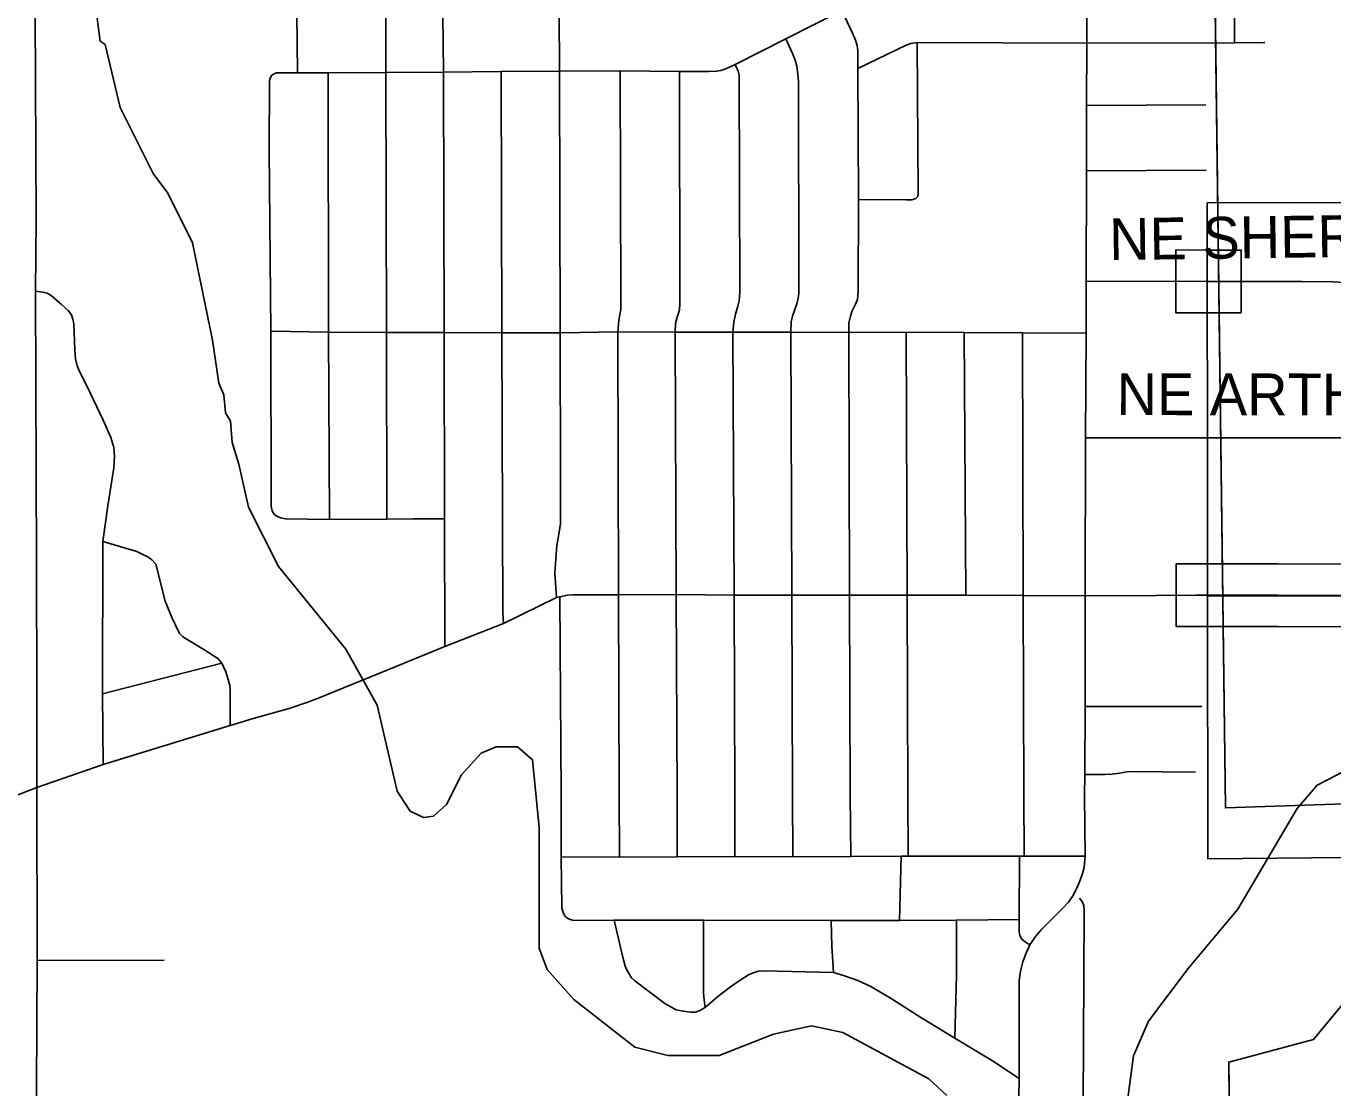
# Model space of a CAD drawing. Extents: x -1403959 to 81668, y -1400582 to 11018.
# Drawn here: x 7531.9 to 7652.7, y 8382.1 to 8480.3 of the extents above; entities that cross this region are included whole.
import ezdxf

# ---------------------------------------------------------------- set-up
doc = ezdxf.new("R2010")
doc.units = 0
for name, color, linetype in [('tdCiCityDivCarto', 7, 'Continuous'), ('tdCiCoBndryTxt', 7, 'Continuous'), ('tdCiRRCL', 7, 'Continuous'), ('tdCiSectLine', 7, 'Continuous'), ('tdCiSectNmbr', 7, 'Continuous'), ('tdCiSectTwpRng', 7, 'Continuous'), ('tdCoCityStreetMajor', 7, 'Continuous'), ('tdCoClipBndry', 7, 'Continuous'), ('tdCoSectNmbr', 7, 'Continuous'), ('tdCoSurfBitum', 7, 'Continuous'), ('tdCoTwpNameTxt', 7, 'Continuous')]:
    doc.layers.add(name, color=color, linetype=linetype)

msp = doc.modelspace()

# ---------------------------------------------------------------- linework, layer by layer
at = {"layer": 'tdCiCityDivCarto'}
for points in [[(7641.31, 8456.71), (7649.82, 8456.69), (7652.72, 8456.68), (7653.72, 8456.62), (7654.52, 8456.5), (7655.07, 8456.37), (7655.61, 8456.12), (7655.96, 8455.95), (7656.41, 8455.67), (7656.79, 8455.33), (7657, 8454.96)], [(7641.23, 8442.26), (7659.37, 8442.25)]]:
    msp.add_lwpolyline(points, dxfattribs=at)
at = {"layer": 'tdCiCoBndryTxt'}
for points in [[(7641.08, 8456.71), (7641.31, 8456.71)], [(7641.11, 8427.7), (7647.61, 8427.71), (7660.14, 8427.68)]]:
    msp.add_lwpolyline(points, dxfattribs=at)
at = {"layer": 'tdCiRRCL'}
msp.add_lwpolyline([(7653.92, 8403.46), (7641.13, 8403.32), (7641.11, 8427.7), (7641.09, 8442.26), (7641.08, 8456.71), (7641.07, 8463.96), (7654.26, 8463.99)], dxfattribs=at)
at = {"layer": 'tdCiSectLine'}
for points in [[(7644.21, 8453.81), (7641.31, 8453.81), (7641.08, 8453.81), (7638.18, 8453.81), (7638.18, 8459.62), (7641.08, 8459.61), (7641.32, 8459.61), (7644.22, 8459.61), (7644.21, 8453.81)], [(7660.13, 8424.78), (7647.61, 8424.8), (7641.11, 8424.79), (7638.21, 8424.79), (7638.2, 8430.59), (7641.1, 8430.6), (7647.6, 8430.61), (7647.61, 8430.61), (7647.61, 8430.61), (7660.15, 8430.58)]]:
    msp.add_lwpolyline(points, dxfattribs=at)
at = {"layer": 'tdCiSectNmbr'}
for points in [[(7629.95, 8478.75), (7629.94, 8484.22), (7629.99, 8497.53), (7630.01, 8503.02), (7630, 8508.7), (7630.04, 8518.58), (7630.02, 8524.33)], [(7629.78, 8427.64), (7629.82, 8442.26), (7629.87, 8451.91), (7629.88, 8456.72), (7629.91, 8466.94), (7629.92, 8472.98), (7629.95, 8478.75)], [(7629.82, 8442.26), (7641.23, 8442.26)], [(7566.13, 8421.14), (7570.58, 8422.95), (7576.01, 8425.09), (7580.9, 8427.48), (7580.9, 8427.48)], [(7580.9, 8427.48), (7581.22, 8427.56), (7581.93, 8427.69), (7582.4, 8427.74), (7583.11, 8427.74), (7586.64, 8427.73), (7591.96, 8427.75), (7597.34, 8427.69), (7602.65, 8427.69), (7608.01, 8427.69), (7613.34, 8427.69), (7618.74, 8427.69), (7624.05, 8427.67), (7629.78, 8427.64)], [(7629.78, 8403.57), (7629.72, 8409.18), (7629.76, 8411.13), (7629.78, 8417.42), (7629.78, 8427.64)], [(7629.78, 8427.64), (7636.38, 8427.67), (7640.02, 8427.69), (7641.11, 8427.7)], [(7532.85, 8409.93), (7538.97, 8412.05), (7550.74, 8415.64), (7553.08, 8416.35), (7556.18, 8417.23), (7557.82, 8417.77), (7558.96, 8418.21), (7560.31, 8418.77), (7566.13, 8421.14), (7566.13, 8421.14)], [(7490.96, 8397.59), (7495.51, 8398.45), (7497.48, 8398.84), (7504, 8400.12), (7509.51, 8401.19), (7510.18, 8401.38), (7510.85, 8401.57), (7511.56, 8401.78), (7512.26, 8402.02), (7516.16, 8403.45), (7518.49, 8404.34), (7520.06, 8404.95), (7523.36, 8406.24), (7532.85, 8409.93), (7532.85, 8409.93)], [(7628.7, 8400), (7629.1, 8400.82), (7629.36, 8401.43), (7629.54, 8401.97), (7629.68, 8402.53), (7629.78, 8403.57)], [(7624.67, 8395.36), (7625.19, 8396.14), (7625.76, 8396.78), (7627.72, 8398.75), (7628.24, 8399.32), (7628.7, 8400)], [(7623.62, 8379.3), (7623.67, 8383.01), (7623.69, 8392.08), (7623.81, 8392.94), (7624.01, 8393.8), (7624.3, 8394.55), (7624.67, 8395.36)]]:
    msp.add_lwpolyline(points, dxfattribs=at)
at = {"layer": 'tdCiSectTwpRng'}
for points in [[(7570.44, 8476.07), (7570.39, 8481.39), (7570.34, 8499.05), (7570.31, 8513.13), (7570.28, 8513.75), (7570.13, 8514.22), (7569.92, 8514.59), (7566.6, 8519.37), (7566.15, 8520), (7566, 8520.22)], [(7643.59, 8478.77), (7643.6, 8483.6), (7643.64, 8497.55), (7643.66, 8503.02), (7643.67, 8508.73), (7643.69, 8518.57)], [(7556.94, 8475.98), (7556.9, 8481.45), (7556.88, 8499.29), (7556.88, 8507.81), (7556.75, 8508.43), (7556.56, 8508.9), (7556.41, 8509.19), (7555.02, 8511.2)], [(7565.12, 8476.03), (7565.12, 8481.45), (7564.99, 8498.97), (7564.97, 8508.24), (7564.97, 8508.54), (7564.91, 8508.85), (7564.78, 8509.13), (7564.39, 8509.69)], [(7580.9, 8427.48), (7580.75, 8429.73), (7580.83, 8431.04), (7580.94, 8432.29), (7581.14, 8433.51), (7581.26, 8434.32), (7581.27, 8438.41), (7581.23, 8451.97), (7581.19, 8476.14), (7581.16, 8481.58), (7581.11, 8486.89), (7581.05, 8492.22), (7581.05, 8497.67), (7581.02, 8499.19), (7581, 8503.09)], [(7608.01, 8427.69), (7607.94, 8452), (7607.94, 8452.88), (7608.09, 8453.5), (7608.24, 8454), (7608.55, 8454.61), (7608.72, 8455.05), (7608.81, 8455.78), (7608.83, 8464.29), (7608.78, 8476.4), (7608.76, 8478.02), (7608.7, 8478.53), (7608.56, 8479), (7608.28, 8479.67), (7607.29, 8481.76), (7606.1, 8484.19), (7605.9, 8484.8), (7605.79, 8485.44), (7605.8, 8486.84), (7605.77, 8492.2), (7605.73, 8497.59)], [(7532.84, 8418.58), (7532.81, 8430.66), (7532.71, 8455.8), (7532.78, 8462.46), (7532.7, 8481.49), (7532.74, 8492.2)], [(7554.59, 8475.77), (7554.78, 8475.9), (7555, 8475.98), (7556.94, 8475.98), (7559.78, 8475.99), (7565.12, 8476.03), (7570.44, 8476.07), (7575.79, 8476.13), (7581.19, 8476.14), (7586.8, 8476.17), (7592.27, 8476.13), (7594.97, 8476.12), (7595.68, 8476.14), (7596.11, 8476.22), (7596.56, 8476.37), (7597.43, 8476.75), (7602.1, 8479.13), (7607.29, 8481.76)], [(7602.65, 8427.69), (7602.57, 8452.01), (7602.6, 8452.98), (7602.73, 8453.49), (7603.11, 8454.63), (7603.24, 8455.16), (7603.3, 8455.59), (7603.31, 8456.28), (7603.27, 8475.2), (7603.22, 8475.88), (7603.13, 8476.61), (7602.96, 8477.17), (7602.73, 8477.77), (7602.1, 8479.13)], [(7608.78, 8476.4), (7613.24, 8478.55), (7613.68, 8478.71), (7614.25, 8478.8), (7629.95, 8478.75)], [(7614.16, 8464.4), (7614.3, 8464.57), (7614.34, 8464.85), (7614.25, 8478.8)], [(7629.95, 8478.75), (7643.59, 8478.77)], [(7643.59, 8478.77), (7646.32, 8478.8)], [(7646.32, 8478.8), (7646.39, 8478.8)], [(7597.34, 8427.69), (7597.22, 8452.02), (7597.29, 8452.94), (7597.44, 8453.68), (7597.67, 8454.41), (7597.79, 8454.92), (7597.84, 8455.7), (7597.78, 8475.77), (7597.7, 8476.14), (7597.43, 8476.75)], [(7554.84, 8435.17), (7554.7, 8435.31), (7554.61, 8435.53), (7554.53, 8435.89), (7554.51, 8436.28), (7554.5, 8452.1), (7554.34, 8468.83), (7554.36, 8475.27), (7554.44, 8475.55), (7554.59, 8475.77)], [(7559.82, 8452.01), (7559.78, 8475.99)], [(7565.22, 8434.73), (7565.17, 8451.98), (7565.12, 8476.03)], [(7570.58, 8422.95), (7570.54, 8434.76), (7570.52, 8451.99), (7570.44, 8476.07)], [(7576.01, 8425.09), (7575.93, 8426.1), (7575.86, 8451.96), (7575.79, 8476.13)], [(7586.64, 8427.73), (7586.57, 8452.06), (7586.68, 8453.14), (7586.84, 8454.11), (7586.85, 8454.85), (7586.8, 8476.17)], [(7591.96, 8427.75), (7591.88, 8452.03), (7591.92, 8452.85), (7591.99, 8453.19), (7592.29, 8454.08), (7592.32, 8454.64), (7592.27, 8476.13)], [(7629.92, 8472.98), (7640.94, 8473.02)], [(7629.91, 8466.94), (7640.98, 8467)], [(7608.83, 8464.29), (7613.24, 8464.24), (7613.77, 8464.24), (7614.13, 8464.36), (7614.16, 8464.4)], [(7629.88, 8456.72), (7641.08, 8456.71)], [(7538.97, 8412.05), (7538.91, 8418.59), (7538.94, 8432.66), (7539.42, 8435.96), (7539.97, 8439.48), (7540.04, 8440.55), (7539.96, 8441.36), (7539.7, 8442.29), (7538.98, 8443.87), (7537.49, 8446.99), (7536.81, 8448.31), (7536.58, 8448.9), (7536.42, 8449.54), (7536.36, 8450.34), (7536.28, 8452.78), (7536.19, 8453.21), (7536.04, 8453.63), (7535.73, 8454.01), (7535.12, 8454.57), (7534.18, 8455.4), (7533.79, 8455.61), (7533.41, 8455.73), (7532.71, 8455.8)], [(7554.5, 8452.1), (7559.82, 8452.01)], [(7559.9, 8434.71), (7559.82, 8452.01)], [(7559.82, 8452.01), (7565.17, 8451.98), (7570.52, 8451.99), (7575.86, 8451.96), (7581.23, 8451.97)], [(7581.23, 8451.97), (7586.57, 8452.06), (7591.88, 8452.03), (7597.22, 8452.02), (7602.57, 8452.01), (7607.94, 8452), (7613.24, 8452.01), (7618.61, 8452), (7623.98, 8451.96), (7629.87, 8451.91)], [(7613.34, 8427.69), (7613.24, 8452.01)], [(7618.74, 8427.69), (7618.61, 8452)], [(7624.05, 8427.67), (7623.98, 8451.96)], [(7554.84, 8435.16), (7555.03, 8434.99), (7555.39, 8434.84), (7555.87, 8434.75), (7557.83, 8434.73), (7559.9, 8434.71), (7565.22, 8434.73), (7567.61, 8434.75), (7570.54, 8434.76)], [(7538.94, 8432.66), (7542.1, 8431.75), (7542.66, 8431.47), (7543.1, 8431.23), (7543.49, 8430.97)], [(7549.96, 8421.42), (7549.59, 8421.85), (7548.28, 8422.69), (7546.34, 8423.86), (7546.04, 8424.15), (7545.36, 8425.56), (7544.71, 8427.15), (7543.85, 8430.56), (7543.49, 8430.97)], [(7581.34, 8403.52), (7581.33, 8409.28), (7581.22, 8427.56)], [(7586.72, 8403.48), (7586.69, 8409.26), (7586.64, 8427.73)], [(7592.07, 8403.51), (7592.06, 8409.23), (7591.96, 8427.75)], [(7597.39, 8403.54), (7597.38, 8409.19), (7597.34, 8427.69)], [(7602.75, 8403.52), (7602.72, 8409.26), (7602.65, 8427.69)], [(7608.11, 8403.55), (7608.06, 8409.21), (7608.01, 8427.69)], [(7613.43, 8403.58), (7613.4, 8409.25), (7613.34, 8427.69)], [(7624.14, 8403.57), (7624.13, 8409.28), (7624.05, 8427.67)], [(7538.91, 8418.59), (7549.96, 8421.42)], [(7550.74, 8415.64), (7550.74, 8418.78), (7550.69, 8419.36), (7550.49, 8420.11), (7550.33, 8420.61), (7549.96, 8421.42)], [(7532.85, 8409.93), (7532.85, 8409.93), (7532.84, 8418.58)], [(7629.78, 8417.42), (7640.57, 8417.4)], [(7629.76, 8411.13), (7631.61, 8411.12), (7632.28, 8411.14), (7632.96, 8411.24), (7633.84, 8411.39), (7639.98, 8411.33)], [(7532.86, 8360.93), (7532.86, 8360.93), (7532.86, 8367.01), (7532.84, 8371.7), (7532.86, 8372.87), (7532.82, 8378.93), (7532.82, 8382.07), (7532.88, 8393.91), (7532.85, 8409.93)], [(7581.34, 8403.52), (7586.72, 8403.48), (7592.07, 8403.51), (7597.39, 8403.54), (7602.75, 8403.52), (7608.11, 8403.55), (7612.78, 8403.58), (7613.43, 8403.58), (7623.71, 8403.57), (7624.14, 8403.57), (7629.78, 8403.57)], [(7581.61, 8398.15), (7581.58, 8398.21), (7581.49, 8398.46), (7581.4, 8398.8), (7581.34, 8403.52)], [(7612.61, 8397.62), (7612.78, 8403.58)], [(7624.67, 8395.36), (7624.27, 8395.61), (7623.94, 8395.89), (7623.76, 8396.23), (7623.69, 8396.6), (7623.67, 8397.7), (7623.71, 8403.57)], [(7629.32, 8379.76), (7629.34, 8379.77), (7629.49, 8380.07), (7629.6, 8380.6), (7629.69, 8398.51), (7629.66, 8399), (7629.52, 8399.38), (7629.25, 8399.68)], [(7581.61, 8398.15), (7581.74, 8397.96)], [(7581.74, 8397.96), (7582.01, 8397.77), (7582.39, 8397.65), (7582.74, 8397.63), (7586.22, 8397.65), (7594.49, 8397.65), (7606.3, 8397.63), (7612.61, 8397.62), (7617.89, 8397.66), (7623.67, 8397.7)], [(7586.22, 8397.65), (7586.84, 8394.99), (7587.1, 8393.98), (7587.28, 8393.31), (7587.52, 8392.83), (7587.85, 8392.32), (7588.16, 8392.04), (7590.91, 8389.96), (7591.98, 8389.37), (7592.63, 8389.23), (7593.31, 8389.15), (7593.75, 8389.15), (7594.15, 8389.3), (7594.65, 8389.59)], [(7594.65, 8389.59), (7594.53, 8390.53), (7594.49, 8390.99), (7594.49, 8397.65)], [(7606.5, 8392.8), (7606.37, 8395.26), (7606.3, 8397.63)], [(7617.74, 8386.73), (7617.9, 8392.64), (7617.89, 8397.66)], [(7532.88, 8393.91), (7544.63, 8393.95)], [(7594.65, 8389.59), (7595.83, 8390.6), (7597, 8391.48), (7597.89, 8392.09), (7598.66, 8392.61), (7599.09, 8392.79), (7599.59, 8392.94), (7600.04, 8392.96), (7606.5, 8392.8), (7607.53, 8392.5), (7608.76, 8392.06), (7609.98, 8391.52), (7611.94, 8390.34), (7614.6, 8388.66), (7617.74, 8386.73), (7621.22, 8384.64), (7623.67, 8383.01)]]:
    msp.add_lwpolyline(points, dxfattribs=at)
at = {"layer": 'tdCoCityStreetMajor'}
msp.add_lwpolyline([(7641.07, 8427.65), (7663.63, 8427.63)], dxfattribs=at)
at = {"layer": 'tdCoClipBndry'}
msp.add_lwpolyline([(7504.77, 8571.65), (7555.69, 8573.8), (7640.61, 8574.81), (7642.76, 8408.03), (7658.38, 8408.57), (7656.06, 8392.83), (7650.89, 8386.63), (7643.07, 8384.53), (7643.53, 8331.05), (7651.76, 8331.03)], dxfattribs=at)
at = {"layer": 'tdCoSurfBitum'}
for points in [[(7617, 8381.45), (7615.33, 8382.98), (7607.39, 8387.26), (7604.49, 8387.87), (7600.97, 8387.11), (7595.93, 8385.13), (7591.2, 8385.13), (7588.14, 8385.9), (7582.49, 8390.33), (7580.05, 8393.08), (7579.29, 8395.06), (7579.29, 8406.21), (7578.69, 8412.47), (7577.31, 8413.69), (7575.33, 8413.69), (7573.95, 8413.08), (7572.12, 8411.1), (7570.74, 8408.35), (7569.52, 8407.28), (7568.6, 8407.13), (7567.38, 8407.74), (7566.16, 8409.58), (7564.33, 8417.52), (7561.43, 8422.71), (7555.18, 8430.35), (7552.43, 8435.85), (7551.52, 8439.82), (7550.91, 8441.8), (7550.75, 8443.79), (7550.3, 8444.55), (7550.14, 8446.23), (7549.69, 8447.3), (7549.08, 8451.27), (7547.25, 8460.28), (7544.96, 8464.86), (7543.59, 8466.69), (7540.54, 8472.8), (7539.16, 8478.61), (7538.71, 8478.91), (7538.25, 8482.42)], [(7633.65, 8380.52), (7634.26, 8385.1), (7635.64, 8388.31), (7639.31, 8393.19), (7643.89, 8398.68), (7649.39, 8407.99), (7651.23, 8410.13), (7655.05, 8412.11)]]:
    msp.add_lwpolyline(points, dxfattribs=at)
at = {"layer": 'tdCoTwpNameTxt'}
msp.add_lwpolyline([(7555.69, 8573.8), (7640.61, 8574.81), (7641.31, 8520.98), (7642.48, 8429.84), (7642.76, 8408.03), (7658.38, 8408.57), (7656.06, 8392.83), (7650.89, 8386.63), (7643.07, 8384.53), (7644.66, 8261.26), (7645.2, 8219.98), (7646.5, 8118.84), (7647.93, 8008.34), (7648.69, 7949.83)], dxfattribs=at)

# ---------------------------------------------------------------- texts
at = {"layer": 'tdCoSectNmbr'}
for s, height, rotation, p in [('NE SHERIDAN', 3.8691, 0.7943, (7632.03, 8458.67)), ('NE ARTHUR', 3.869, 359.9202, (7632.69, 8444.35))]:
    msp.add_text(s, height=height, rotation=rotation, dxfattribs=at).set_placement(p)

doc.saveas('drawing.dxf')
